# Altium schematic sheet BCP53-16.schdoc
size 127 x 101 mm
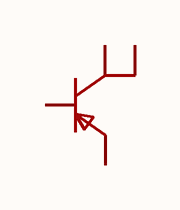
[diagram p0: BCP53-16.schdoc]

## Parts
Q?  bcp53-16_c148109  [SOT-223-3_L6.5-W3.4-P2.30-LS7.0-BR]  (value not drawn)

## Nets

Not connected (* = marked no-connect by the designer): Q? 1(B) 2(C) 3(E) 4(C)

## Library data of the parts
Q? = bcp53-16_c148109: 晶体管类型:PNP;集电极电流(Ic):1A;集射极击穿电压(Vceo):80V;耗散功率(Pd):1.5W;直流电流增益(hFE):100;; Manufacturer: CJ(江苏长电/长晶); AddInBom: yes; ModelId: 925194bf9823436183a3e0b978a8d076; ModelName: SOT-223-4P_L6.5-W3.5-H1.6-LS7.0-P2.30; ModelTransform: 279.89794,255.905,0,180,0,0,-3.9385,-0.0005,0; type: PNP; Current - Collector(Ic): 1A; Collector - Emitter Voltage VCEO: 80V; Pd - Power Dissipation: 1.5W; DC Current Gain: 100; Transition frequency(fT): 100MHz; Current - Collector Cutoff: 100nA; Vce Saturation(VCE(sat)): 500mV; Emitter-Base Voltage(Vebo): 5V; Number: 1个PNP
